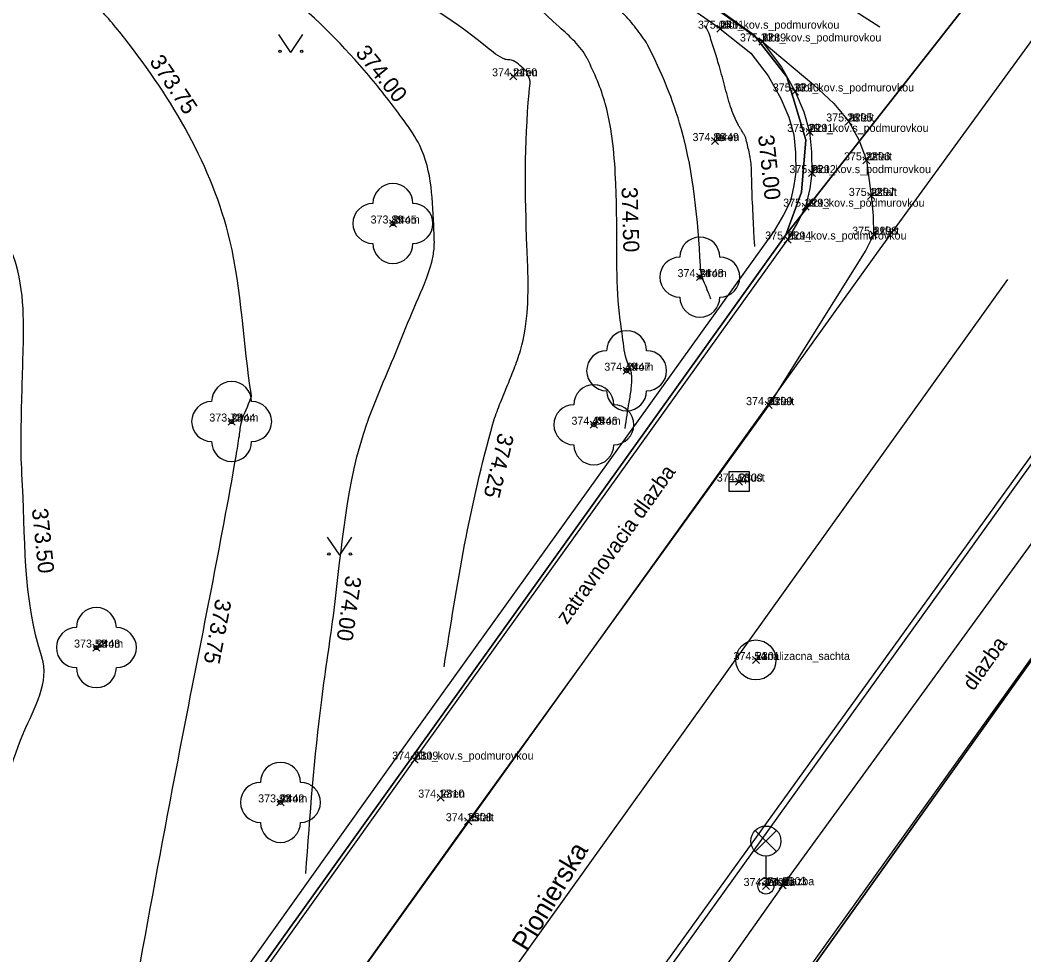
# Model space of a CAD drawing. Extents: x -400488 to -400124, y -1251493 to -1251223.
# Drawn here: x -400289.23 to -400264.14, y -1251377.2 to -1251353.83 of the extents above; entities that cross this region are included whole.
import ezdxf

# ---------------------------------------------------------------- set-up
doc = ezdxf.new("R2010")
doc.units = 0
for name, color, linetype in [('Level 20', 7, 'Continuous'), ('Level 21', 7, 'Continuous'), ('Level 22', 7, 'Continuous'), ('Level 23', 7, 'Continuous'), ('Level 31', 7, 'Continuous'), ('Level 32', 7, 'Continuous'), ('Level 35', 7, 'Continuous'), ('Level 36', 7, 'Continuous'), ('Level 49', 7, 'Continuous'), ('Level 52', 7, 'Continuous'), ('Level 53', 7, 'Continuous'), ('Level 63', 7, 'Continuous')]:
    doc.layers.add(name, color=color, linetype=linetype)

msp = doc.modelspace()

# ---------------------------------------------------------------- linework, layer by layer
at = {"layer": 'Level 20'}
for p, q in [((-400271.818, -1251354.138), (-400271.642, -1251353.962)), ((-400271.642, -1251354.138), (-400271.818, -1251353.962)), ((-400270.768, -1251354.458), (-400270.592, -1251354.282)), ((-400270.592, -1251354.458), (-400270.768, -1251354.282)), ((-400276.988, -1251355.328), (-400276.812, -1251355.152)), ((-400276.812, -1251355.328), (-400276.988, -1251355.152)), ((-400269.948, -1251355.708), (-400269.772, -1251355.532)), ((-400269.772, -1251355.708), (-400269.948, -1251355.532)), ((-400268.608, -1251356.458), (-400268.432, -1251356.282)), ((-400268.432, -1251356.458), (-400268.608, -1251356.282)), ((-400269.588, -1251356.718), (-400269.412, -1251356.542)), ((-400269.412, -1251356.718), (-400269.588, -1251356.542)), ((-400271.948, -1251356.948), (-400271.772, -1251356.772)), ((-400271.772, -1251356.948), (-400271.948, -1251356.772)), ((-400268.168, -1251357.428), (-400267.992, -1251357.252)), ((-400267.992, -1251357.428), (-400268.168, -1251357.252)), ((-400269.528, -1251357.748), (-400269.352, -1251357.572)), ((-400269.352, -1251357.748), (-400269.528, -1251357.572)), ((-400268.048, -1251358.318), (-400267.872, -1251358.142)), ((-400267.872, -1251358.318), (-400268.048, -1251358.142)), ((-400269.688, -1251358.588), (-400269.512, -1251358.412)), ((-400269.512, -1251358.588), (-400269.688, -1251358.412)), ((-400279.998, -1251359.008), (-400279.822, -1251358.832)), ((-400279.822, -1251359.008), (-400279.998, -1251358.832)), ((-400270.138, -1251359.408), (-400269.962, -1251359.232)), ((-400269.962, -1251359.408), (-400270.138, -1251359.232)), ((-400267.988, -1251359.288), (-400267.812, -1251359.112)), ((-400267.812, -1251359.288), (-400267.988, -1251359.112)), ((-400272.328, -1251360.348), (-400272.152, -1251360.172)), ((-400272.152, -1251360.348), (-400272.328, -1251360.172)), ((-400274.158, -1251362.688), (-400273.982, -1251362.512)), ((-400273.982, -1251362.688), (-400274.158, -1251362.512)), ((-400270.608, -1251363.548), (-400270.432, -1251363.372)), ((-400270.432, -1251363.548), (-400270.608, -1251363.372)), ((-400284.028, -1251363.958), (-400283.852, -1251363.782)), ((-400283.852, -1251363.958), (-400284.028, -1251363.782)), ((-400274.978, -1251364.038), (-400274.802, -1251363.862)), ((-400274.802, -1251364.038), (-400274.978, -1251363.862)), ((-400271.348, -1251365.458), (-400271.172, -1251365.282)), ((-400271.172, -1251365.458), (-400271.348, -1251365.282)), ((-400287.408, -1251369.608), (-400287.232, -1251369.432)), ((-400287.232, -1251369.608), (-400287.408, -1251369.432)), ((-400270.928, -1251369.918), (-400270.752, -1251369.742)), ((-400270.752, -1251369.918), (-400270.928, -1251369.742)), ((-400279.458, -1251372.408), (-400279.282, -1251372.232)), ((-400279.282, -1251372.408), (-400279.458, -1251372.232)), ((-400282.808, -1251373.478), (-400282.632, -1251373.302)), ((-400282.632, -1251373.478), (-400282.808, -1251373.302)), ((-400278.808, -1251373.358), (-400278.632, -1251373.182)), ((-400278.632, -1251373.358), (-400278.808, -1251373.182)), ((-400278.118, -1251373.948), (-400277.942, -1251373.772)), ((-400277.942, -1251373.948), (-400278.118, -1251373.772)), ((-400270.678, -1251375.568), (-400270.502, -1251375.392)), ((-400270.502, -1251375.568), (-400270.678, -1251375.392)), ((-400270.258, -1251375.548), (-400270.082, -1251375.372)), ((-400270.082, -1251375.548), (-400270.258, -1251375.372))]:
    msp.add_line(p, q, dxfattribs=at)
at = {"layer": 'Level 31'}
for points in [[(-400252.627, -1251354.111), (-400255.45, -1251357.92), (-400285.456, -1251399.746)], [(-400256.77, -1251357.04), (-400270.17, -1251375.46), (-400275.42, -1251382.91), (-400276.52, -1251382.17), (-400278.7, -1251385.33), (-400277.74, -1251386), (-400287.1, -1251399.16)]]:
    msp.add_lwpolyline(points, dxfattribs=at)
at = {"layer": 'Level 32'}
msp.add_line((-400290.55, -1251396.645), (-400264.548, -1251360.319), dxfattribs=at)
for points in [[(-400313.317, -1251321.122), (-400298.667, -1251332.37), (-400270.618, -1251352.155), (-400270.556, -1251352.196), (-400267.742, -1251354.003)], [(-400270.68, -1251354.37), (-400269.393, -1251355.452), (-400268.89, -1251355.918), (-400268.52, -1251356.37), (-400268.265, -1251356.83), (-400268.08, -1251357.34), (-400267.96, -1251358.23), (-400267.913, -1251358.721), (-400267.9, -1251359.2), (-400268.092, -1251359.586), (-400270.52, -1251363.46), (-400278.03, -1251373.86), (-400293.48, -1251395.44), (-400293.769, -1251395.863), (-400294.17, -1251396.23), (-400294.49, -1251396.36), (-400295.676, -1251396.619), (-400296.86, -1251396.78), (-400297.255, -1251396.759), (-400297.65, -1251396.69), (-400298.36, -1251396.445), (-400298.94, -1251396.17), (-400299.54, -1251395.8), (-400299.67, -1251395.66)], [(-400276.52, -1251382.17), (-400257.84, -1251356.24)]]:
    msp.add_lwpolyline(points, dxfattribs=at)
at = {"layer": 'Level 35'}
for points in [[(-400271.73, -1251354.05), (-400280.61, -1251347.87), (-400289.94, -1251341.22), (-400298.73, -1251334.93), (-400304.55, -1251330.65), (-400304.36, -1251330.4)], [(-400289.76, -1251340.83), (-400270.68, -1251354.37), (-400270.2, -1251355.011), (-400269.86, -1251355.62), (-400269.639, -1251356.125), (-400269.5, -1251356.63), (-400269.449, -1251357.125), (-400269.44, -1251357.66), (-400269.496, -1251358.046), (-400269.6, -1251358.5), (-400269.799, -1251358.893), (-400270.05, -1251359.32), (-400279.37, -1251372.32), (-400292.97, -1251391.4)], [(-400271.73, -1251354.05), (-400270.963, -1251354.66), (-400270.536, -1251355.23), (-400270.219, -1251355.798), (-400270.017, -1251356.259), (-400269.894, -1251356.704), (-400269.849, -1251357.149), (-400269.84, -1251357.634), (-400269.89, -1251357.973), (-400269.979, -1251358.363), (-400270.151, -1251358.701), (-400270.386, -1251359.102), (-400279.695, -1251372.087), (-400293.283, -1251391.15)]]:
    msp.add_lwpolyline(points, dxfattribs=at)
at = {"layer": 'Level 36'}
for p, q in [((-400282.46, -1251354.644), (-400282.76, -1251354.194)), ((-400282.46, -1251354.644), (-400282.16, -1251354.194)), ((-400281.241, -1251367.209), (-400281.541, -1251366.759)), ((-400281.241, -1251367.209), (-400280.941, -1251366.759))]:
    msp.add_line(p, q, dxfattribs=at)
for centre, radius in [((-400282.73, -1251354.614), 0.03), ((-400282.19, -1251354.614), 0.03), ((-400279.91, -1251358.92), 0.05), ((-400272.24, -1251360.26), 0.05), ((-400274.07, -1251362.6), 0.05), ((-400283.94, -1251363.87), 0.05), ((-400274.89, -1251363.95), 0.05), ((-400281.511, -1251367.179), 0.03), ((-400280.971, -1251367.179), 0.03), ((-400287.32, -1251369.52), 0.05), ((-400282.72, -1251373.39), 0.05)]:
    msp.add_circle(centre, radius, dxfattribs=at)
for centre, start, end in [((-400279.91, -1251358.42), 0, 180), ((-400280.41, -1251358.92), 90, 270), ((-400279.41, -1251358.92), 270, 90), ((-400272.24, -1251359.76), 0, 180), ((-400279.91, -1251359.42), 180, 0), ((-400272.74, -1251360.26), 90, 270), ((-400271.74, -1251360.26), 270, 90), ((-400272.24, -1251360.76), 180, 0), ((-400274.07, -1251362.1), 0, 180), ((-400274.57, -1251362.6), 90, 270), ((-400273.57, -1251362.6), 270, 90), ((-400283.94, -1251363.37), 0, 180), ((-400274.89, -1251363.45), 0, 180), ((-400274.07, -1251363.1), 180, 0), ((-400284.44, -1251363.87), 90, 270), ((-400283.44, -1251363.87), 270, 90), ((-400275.39, -1251363.95), 90, 270), ((-400274.39, -1251363.95), 270, 90), ((-400283.94, -1251364.37), 180, 0), ((-400274.89, -1251364.45), 180, 0), ((-400287.32, -1251369.02), 0, 180), ((-400287.82, -1251369.52), 90, 270), ((-400286.82, -1251369.52), 270, 90), ((-400287.32, -1251370.02), 180, 0), ((-400282.72, -1251372.89), 0, 180), ((-400283.22, -1251373.39), 90, 270), ((-400282.22, -1251373.39), 270, 90), ((-400282.72, -1251373.89), 180, 0)]:
    msp.add_arc(centre, 0.5, start, end, dxfattribs=at)
at = {"layer": 'Level 49'}
for points in [[(-400278.631, -1251370.004), (-400278.118, -1251366.954), (-400277.412, -1251363.928), (-400277.404, -1251363.9), (-400277.243, -1251363.447), (-400277.063, -1251363.002), (-400276.883, -1251362.554), (-400276.725, -1251362.096), (-400276.548, -1251361.022), (-400276.561, -1251359.49), (-400276.508, -1251355.66), (-400276.495, -1251355.542), (-400276.499, -1251355.304), (-400276.5, -1251355.302), (-400276.561, -1251355.147), (-400276.562, -1251355.145), (-400276.659, -1251355.037), (-400276.991, -1251354.829), (-400277.106, -1251354.817), (-400277.114, -1251354.814), (-400277.554, -1251354.518), (-400280.527, -1251352.524), (-400282.011, -1251351.524), (-400282.752, -1251351.021), (-400283.123, -1251350.771), (-400283.308, -1251350.645), (-400283.491, -1251350.515), (-400283.5, -1251350.503), (-400283.513, -1251350.487), (-400283.613, -1251350.393), (-400283.723, -1251350.31), (-400283.834, -1251350.228), (-400283.937, -1251350.138), (-400285.14, -1251348.868), (-400286.294, -1251347.546), (-400287.449, -1251346.222), (-400288.656, -1251344.945), (-400289.834, -1251343.824), (-400290.459, -1251343.304), (-400291.116, -1251342.818), (-400291.123, -1251342.814), (-400295.387, -1251340.816), (-400295.481, -1251340.776), (-400295.888, -1251340.55), (-400296.417, -1251340.117), (-400298.55, -1251337.977), (-400299.765, -1251336.773), (-400300.345, -1251336.13), (-400300.624, -1251335.775), (-400300.759, -1251335.587), (-400300.892, -1251335.391), (-400300.889, -1251335.373), (-400300.892, -1251335.36), (-400300.967, -1251335.291), (-400301.043, -1251335.241), (-400301.201, -1251335.182), (-400301.531, -1251335.135), (-400302.215, -1251335.034), (-400302.251, -1251335.031), (-400302.332, -1251334.999), (-400303.687, -1251334.283), (-400305.005, -1251333.533), (-400306.96, -1251332.166)], [(-400282.087, -1251375.169), (-400281.69, -1251370.822), (-400281.381, -1251368.586), (-400280.551, -1251363.9), (-400280.546, -1251363.886), (-400280.15, -1251362.887), (-400279.737, -1251361.896), (-400279.326, -1251360.9), (-400278.941, -1251359.886), (-400278.883, -1251359.562), (-400278.885, -1251359.094), (-400279.241, -1251356.971), (-400279.631, -1251356.354), (-400280.512, -1251355.223), (-400282.534, -1251353.186), (-400283.018, -1251352.792), (-400283.53, -1251352.437), (-400284.027, -1251352.07), (-400284.466, -1251351.641), (-400284.483, -1251351.618), (-400284.488, -1251351.612), (-400285.314, -1251350.99), (-400287.151, -1251349.31), (-400292.845, -1251345.168), (-400292.862, -1251345.159), (-400295.431, -1251343.95), (-400295.488, -1251343.921), (-400297.591, -1251342.594), (-400300.391, -1251340.357), (-400303.398, -1251337.509), (-400303.407, -1251337.499), (-400305.011, -1251335.906), (-400306.002, -1251335.061), (-400307.028, -1251334.259), (-400308.006, -1251333.512)], [(-400287.056, -1251382.036), (-400285.095, -1251371.378), (-400283.83, -1251364.736), (-400283.748, -1251364.223), (-400283.689, -1251363.872), (-400283.457, -1251363.276), (-400283.446, -1251363.218), (-400283.447, -1251363.211), (-400283.984, -1251359.342), (-400286.608, -1251354.299), (-400287.35, -1251353.443), (-400287.372, -1251353.421), (-400290.829, -1251350.218), (-400294.574, -1251347.519), (-400294.601, -1251347.503), (-400295.474, -1251347.083), (-400295.494, -1251347.073), (-400299.293, -1251344.638), (-400304.542, -1251340.608), (-400305.224, -1251339.982), (-400305.246, -1251339.958), (-400308.629, -1251336.24), (-400309.532, -1251335.395)], [(-400298.594, -1251390.918), (-400297.579, -1251389.803), (-400296.576, -1251388.675), (-400295.294, -1251386.973), (-400294.717, -1251386.031), (-400294.176, -1251385.068), (-400293.64, -1251384.103), (-400293.079, -1251383.154), (-400292.558, -1251382.354), (-400292.017, -1251381.567), (-400291.474, -1251380.779), (-400290.946, -1251379.978), (-400290.936, -1251379.958), (-400290.353, -1251377.108), (-400290.345, -1251377.073), (-400289.148, -1251371.673), (-400289.131, -1251371.633), (-400288.68, -1251369.757), (-400288.682, -1251369.751), (-400289.179, -1251365.184), (-400289.187, -1251365.045), (-400289.199, -1251364.086), (-400289.178, -1251363.127), (-400289.151, -1251362.167), (-400289.146, -1251361.208), (-400289.326, -1251359.947), (-400289.998, -1251358.61), (-400290.194, -1251358.383), (-400290.2, -1251358.378), (-400291.608, -1251356.855), (-400292.307, -1251356.088), (-400293.021, -1251355.336), (-400293.116, -1251355.24), (-400296.365, -1251351.788), (-400297.616, -1251350.178), (-400299.549, -1251347.891), (-400299.559, -1251347.877), (-400299.595, -1251347.847), (-400301.142, -1251346.859), (-400302.556, -1251345.879), (-400307.962, -1251342.189), (-400307.971, -1251342.179), (-400307.982, -1251342.152), (-400308.883, -1251340.471), (-400309.528, -1251339.56), (-400310.26, -1251338.706), (-400310.968, -1251337.837), (-400311.406, -1251337.164)], [(-400274.109, -1251364.042), (-400274.008, -1251363.383), (-400273.954, -1251363.053), (-400273.943, -1251362.724), (-400273.958, -1251362.626), (-400273.997, -1251362.507), (-400274.011, -1251362.47), (-400274.012, -1251362.468), (-400274.162, -1251361.825), (-400274.25, -1251361.177), (-400274.313, -1251359.872), (-400274.338, -1251357.988), (-400274.341, -1251357.92), (-400274.598, -1251355.942), (-400274.603, -1251355.924), (-400275.052, -1251354.804), (-400275.058, -1251354.792), (-400275.759, -1251354.005), (-400278.319, -1251352.191), (-400278.397, -1251352.171), (-400278.453, -1251352.154), (-400281.685, -1251349.955), (-400282.516, -1251349.39), (-400282.517, -1251349.388), (-400282.537, -1251349.359), (-400282.59, -1251349.305), (-400284.983, -1251346.43), (-400288.552, -1251342.393)], [(-400271.965, -1251360.814), (-400272.009, -1251360.689), (-400272.186, -1251360.237), (-400272.197, -1251360.198), (-400272.225, -1251359.97), (-400272.697, -1251356.579), (-400272.706, -1251356.547), (-400273.542, -1251354.461), (-400273.554, -1251354.438), (-400273.691, -1251354.234), (-400273.837, -1251354.037), (-400274.155, -1251353.667), (-400274.498, -1251353.316), (-400274.859, -1251352.974), (-400275.963, -1251351.93), (-400277.098, -1251350.932), (-400277.684, -1251350.485), (-400277.992, -1251350.283), (-400278.313, -1251350.095), (-400278.97, -1251349.772), (-400279.657, -1251349.533), (-400279.687, -1251349.525), (-400279.791, -1251349.497), (-400280.227, -1251349.321), (-400280.628, -1251349.067), (-400281.363, -1251348.446), (-400281.375, -1251348.435), (-400282.483, -1251347.375), (-400283.583, -1251346.308), (-400284.682, -1251345.24), (-400284.836, -1251345.091)], [(-400270.868, -1251359.496), (-400270.87, -1251359.457), (-400270.883, -1251359.266), (-400270.902, -1251358.882), (-400270.937, -1251358.114), (-400270.945, -1251357.817), (-400270.948, -1251357.668), (-400270.953, -1251357.519), (-400271.011, -1251357.128), (-400271.093, -1251356.785), (-400271.096, -1251356.773), (-400271.106, -1251356.748), (-400271.146, -1251356.676), (-400271.189, -1251356.607), (-400271.233, -1251356.537), (-400271.273, -1251356.466), (-400271.472, -1251356.005), (-400271.551, -1251355.736), (-400271.625, -1251355.466), (-400271.697, -1251355.196), (-400271.773, -1251354.927), (-400271.897, -1251354.522), (-400271.963, -1251354.32), (-400272.032, -1251354.119), (-400272.05, -1251354.084), (-400272.129, -1251353.967)]]:
    msp.add_spline(points, degree=3, dxfattribs=at)
at = {"layer": 'Level 52'}
msp.add_lwpolyline([(-400271.51, -1251365.37), (-400271.51, -1251365.12), (-400271.01, -1251365.12), (-400271.01, -1251365.37)], dxfattribs=at)
msp.add_lwpolyline([(-400271.51, -1251365.37), (-400271.01, -1251365.37), (-400271.01, -1251365.62), (-400271.51, -1251365.62)], close=True, dxfattribs=at)
msp.add_circle((-400270.84, -1251369.83), 0.5, dxfattribs=at)
at = {"layer": 'Level 53'}
for p, q in [((-400270.855, -1251374.62), (-400270.325, -1251374.09)), ((-400270.325, -1251374.09), (-400270.855, -1251374.62)), ((-400270.325, -1251374.62), (-400270.855, -1251374.09)), ((-400270.59, -1251374.73), (-400270.59, -1251375.28))]:
    msp.add_line(p, q, dxfattribs=at)
for centre, radius in [((-400270.59, -1251374.355), 0.375), ((-400270.59, -1251375.48), 0.2)]:
    msp.add_circle(centre, radius, dxfattribs=at)
at = {"layer": 'Level 63'}
for p, q in [((-400308.16, -1251327.55), (-400270.88, -1251354.21)), ((-400270.88, -1251354.21), (-400308.16, -1251327.55)), ((-400250.33, -1251335.59), (-400267.74, -1251359.55)), ((-400244.75, -1251338.16), (-400287.97, -1251398.37)), ((-400270.09, -1251359.2), (-400265.38, -1251353.2)), ((-400265.38, -1251353.2), (-400270.09, -1251359.2)), ((-400270.88, -1251354.21), (-400270.07, -1251355.25)), ((-400270.07, -1251355.25), (-400270.88, -1251354.21)), ((-400270.07, -1251355.25), (-400269.59, -1251356.83)), ((-400269.59, -1251356.83), (-400270.07, -1251355.25)), ((-400269.59, -1251356.83), (-400269.7, -1251358.14)), ((-400269.7, -1251358.14), (-400269.59, -1251356.83)), ((-400274.13, -1251384.12), (-400255.52, -1251358)), ((-400255.52, -1251358), (-400274.13, -1251384.12)), ((-400269.7, -1251358.14), (-400270.09, -1251359.2)), ((-400270.09, -1251359.2), (-400269.7, -1251358.14)), ((-400293.18, -1251391.47), (-400270.09, -1251359.2)), ((-400270.09, -1251359.2), (-400293.18, -1251391.47)), ((-400267.74, -1251359.55), (-400294.25, -1251396.47))]:
    msp.add_line(p, q, dxfattribs=at)

# ---------------------------------------------------------------- texts
at = {"layer": 'Level 21'}
for s, p in [('2451', (-400271.73, -1251354.05)), ('2289', (-400270.68, -1251354.37)), ('2450', (-400276.9, -1251355.24)), ('2290', (-400269.86, -1251355.62)), ('2295', (-400268.52, -1251356.37)), ('2291', (-400269.5, -1251356.63)), ('2449', (-400271.86, -1251356.86)), ('2296', (-400268.08, -1251357.34)), ('2292', (-400269.44, -1251357.66)), ('2297', (-400267.96, -1251358.23)), ('2293', (-400269.6, -1251358.5)), ('2445', (-400279.91, -1251358.92)), ('2298', (-400267.9, -1251359.2)), ('2294', (-400270.05, -1251359.32)), ('2448', (-400272.24, -1251360.26)), ('2447', (-400274.07, -1251362.6)), ('2299', (-400270.52, -1251363.46)), ('2444', (-400283.94, -1251363.87)), ('2446', (-400274.89, -1251363.95)), ('2300', (-400271.26, -1251365.37)), ('2443', (-400287.32, -1251369.52)), ('2301', (-400270.84, -1251369.83)), ('2309', (-400279.37, -1251372.32)), ('2310', (-400278.72, -1251373.27)), ('2442', (-400282.72, -1251373.39)), ('2308', (-400278.03, -1251373.86)), ('2302', (-400270.59, -1251375.48)), ('2303', (-400270.17, -1251375.46))]:
    msp.add_text(s, height=0.2, dxfattribs=at).set_placement(p)
at = {"layer": 'Level 22'}
for s, p in [('plot_kov.s_podmurovkou', (-400271.73, -1251354.05)), ('plot_kov.s_podmurovkou', (-400270.68, -1251354.37)), ('teren', (-400276.9, -1251355.24)), ('plot_kov.s_podmurovkou', (-400269.86, -1251355.62)), ('asfalt', (-400268.52, -1251356.37)), ('plot_kov.s_podmurovkou', (-400269.5, -1251356.63)), ('teren', (-400271.86, -1251356.86)), ('asfalt', (-400268.08, -1251357.34)), ('plot_kov.s_podmurovkou', (-400269.44, -1251357.66)), ('asfalt', (-400267.96, -1251358.23)), ('plot_kov.s_podmurovkou', (-400269.6, -1251358.5)), ('strom', (-400279.91, -1251358.92)), ('asfalt', (-400267.9, -1251359.2)), ('plot_kov.s_podmurovkou', (-400270.05, -1251359.32)), ('strom', (-400272.24, -1251360.26)), ('strom', (-400274.07, -1251362.6)), ('asfalt', (-400270.52, -1251363.46)), ('strom', (-400283.94, -1251363.87)), ('strom', (-400274.89, -1251363.95)), ('vpust', (-400271.26, -1251365.37)), ('strom', (-400287.32, -1251369.52)), ('kanalizacna_sachta', (-400270.84, -1251369.83)), ('plot_kov.s_podmurovkou', (-400279.37, -1251372.32)), ('teren', (-400278.72, -1251373.27)), ('strom', (-400282.72, -1251373.39)), ('asfalt', (-400278.03, -1251373.86)), ('lampa', (-400270.59, -1251375.48)), ('dlazba', (-400270.17, -1251375.46))]:
    msp.add_text(s, height=0.2, dxfattribs=at).set_placement(p)
at = {"layer": 'Level 23'}
for s, p in [('375.05', (-400272.289, -1251354.05)), ('375.33', (-400271.238, -1251354.37)), ('374.21', (-400277.433, -1251355.24)), ('375.33', (-400270.418, -1251355.62)), ('375.26', (-400269.083, -1251356.37)), ('375.29', (-400270.058, -1251356.63)), ('374.86', (-400272.423, -1251356.86)), ('375.22', (-400268.638, -1251357.34)), ('375.26', (-400270.003, -1251357.66)), ('375.12', (-400268.518, -1251358.23)), ('375.19', (-400270.158, -1251358.5)), ('373.89', (-400280.468, -1251358.92)), ('375.11', (-400268.433, -1251359.2)), ('375.15', (-400270.609, -1251359.32)), ('374.74', (-400272.798, -1251360.26)), ('374.49', (-400274.628, -1251362.6)), ('374.80', (-400271.086, -1251363.46)), ('373.73', (-400284.498, -1251363.87)), ('374.45', (-400275.449, -1251363.95)), ('374.68', (-400271.818, -1251365.37)), ('373.58', (-400287.878, -1251369.52)), ('374.54', (-400271.398, -1251369.83)), ('374.23', (-400279.928, -1251372.32)), ('374.17', (-400279.278, -1251373.27)), ('373.93', (-400283.278, -1251373.39)), ('374.15', (-400278.589, -1251373.86)), ('374.47', (-400271.148, -1251375.48)), ('374.51', (-400270.703, -1251375.46))]:
    msp.add_text(s, height=0.2, dxfattribs=at).set_placement(p)
at = {"layer": 'Level 31'}
for s, p in [('zatravnovacia dlazba', (-400275.562, -1251368.964)), ('dlazba', (-400265.403, -1251370.621))]:
    msp.add_text(s, height=0.375, rotation=54.566, dxfattribs=at).set_placement(p)
at = {"layer": 'Level 49'}
for s, rotation, p in [('374.00', 309.0825, (-400280.864, -1251354.661)), ('373.75', 303.7511, (-400286.008, -1251354.87)), ('375.00', 276.0422, (-400270.787, -1251356.722)), ('374.50', 271.7049, (-400274.198, -1251358.01)), ('374.25', 256.6355, (-400277.269, -1251364.134)), ('373.50', 275.9123, (-400288.934, -1251366.055)), ('374.00', 261.9005, (-400281.088, -1251367.705)), ('373.75', 259.063, (-400284.333, -1251368.281))]:
    msp.add_text(s, height=0.4, rotation=rotation, dxfattribs=at).set_placement(p)
at = {"layer": 'Level 63'}
msp.add_text('Pionierska', height=0.48, rotation=59.01, dxfattribs=at).set_placement((-400276.556, -1251377.14))

doc.saveas('drawing.dxf')
